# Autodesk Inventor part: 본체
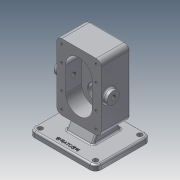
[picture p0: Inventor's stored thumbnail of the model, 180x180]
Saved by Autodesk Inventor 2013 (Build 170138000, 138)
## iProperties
Created: 2020-04
Part Number: 본체
Material: 알루미늄 6061
Document SubType Name: Modeling
Designer: user
Density: 2.71 g/cm^3
Mass: 1478 g
Surface Area: 818.394 cm^2
Volume: 545.387 cm^3
Author: user
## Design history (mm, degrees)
sketch "스케치1"
  geometry: L1 (40, 60)-(-40, 60); L2 (-40, 60)-(-40, -60); L3 (-40, -60)-(40, -60); L4 (40, -60)-(40, 60); L5 (40, 60)-(-40, -60); L6 (-40, 60)-(40, -60); 1 further point
  constraints: 12 end point, 2 midpoint, 2 parallel, 1 horizontal, 1 perpendicular
  dimensions: "d0" = 80 distance of L3.end L2.end; "d1" = 120 distance of L2.end L1.end
extrude "돌출1" new body sketch "스케치1" stored distance "d2" = 53; taper "d3" = 0 deg
fillet "모깎기1" dims "d4" = 9
sketch "스케치2"
  geometry: A1 r 9 centre (-31, -51) between (-40, -51) and (-31, -60) reference; A2 r 9 centre (31, -51) between (31, -60) and (40, -51) reference; A3 r 9 centre (31, 51) between (40, 51) and (31, 60) reference; A4 r 9 centre (-31, 51) between (-31, 60) and (-40, 51) reference; 5 further points
  constraints: 4 coincident
hole "구멍1" sketch "스케치2" at (-31, 51), (31, 51), (31, -51), (-31, -51) diameter "d5" = 4.134; stored, may be unused: countersink angle "d9" = 90 deg, drill point angle "d11" = 118 deg; dims "d6" = 10, "d7" = 4, "d8" = 2, "d10" = 12
sketch "스케치3"
  geometry: L1 (-40, 51)-(-40, -51) reference; L2 (-31, 51)-(-31, 22); L3 (-31, 22)-(-31, -22); A1 r 9 centre (-31, 51) between (-31, 60) and (-40, 51) reference; 3 further points
  constraints: 4 end point, 2 coincident, 1 collinear, 1 parallel
  dimensions: "d12" = 29 distance of L2.start L2.end; "d13" = 44 distance of L2.end L3.end
hole "구멍2" sketch "스케치3" at (-31, 22), (-31, -22) diameter "d14" = 4.134; stored, may be unused: countersink angle "d18" = 90 deg, drill point angle "d20" = 118 deg; dims "d15" = 10, "d16" = 4, "d17" = 2, "d19" = 12
sketch "스케치4"
  geometry: L1 (-24, 22)-(24, 22); L2 (24, 22)-(24, -22); L3 (24, -22)-(-24, -22); L4 (-24, -22)-(-24, 22); L5 (-24, 22)-(24, -22); L6 (24, 22)-(-24, -22); C1 r 24 at (0, 22); C2 r 24 at (0, -22); 1 further point
  constraints: 12 end point, 4 midpoint, 2 centre point, 2 parallel, 1 horizontal, 1 perpendicular
  dimensions: "d21" = 48 distance of L2.end L3.end; "d22" = 44 distance of L1.end L2.end; "d23" = 48 diameter of C1; "d24" = 48 diameter of C2
extrude "돌출2" cut sketch "스케치4" distance "d25" = 29; taper "d26" = 0 deg
sketch "스케치5"
  geometry: L1 (-31, -60)-(31, -60) reference; L2 (0, 0)-(0, 22); C1 r 19 at (0, 22)
  constraints: 2 end point, 1 centre point, 1 coincident, 1 perpendicular
  dimensions: "d27" = 22 distance of L2.start L2.end; "d28" = 38 diameter of C1
extrude "돌출3" join sketch "스케치5" distance "d29" = 17; taper "d30" = 0 deg
sketch "스케치6"
  geometry: A1 r 24 centre (0, 22) between (24, 22) and (-24, 22) reference; 2 further points
  constraints: 1 coincident
hole "구멍3" sketch "스케치6" at (0, 22) diameter "d31" = 17; stored, may be unused: countersink angle "d35" = 90 deg, drill point angle "d37" = 118 deg; dims "d32" = 10, "d33" = 25, "d34" = 15, "d36" = 12
sketch "스케치7"
  geometry: C1 r 12.5 at (0, -22); A1 r 24 centre (0, -22) between (-24, -22) and (24, -22) reference; 1 further point
  constraints: 1 centre point, 1 coincident
  dimensions: "d38" = 25 diameter of C1
extrude "돌출4" cut sketch "스케치7" distance "d39" = 15; taper "d40" = 0 deg
sketch "스케치8"
  geometry: C1 r 8.5 at (0, 0) reference; C2 r 19 at (0, 0) reference; C3 r 14 at (0, 0); 1 further point
  constraints: 1 centre point, 1 coincident
  dimensions: "d41" = 28 diameter of C3
extrude "돌출5" cut sketch "스케치8" distance "d42" = 7.3; taper "d43" = 0 deg
sketch "스케치9"
  geometry: L1 (-53, 0)-(-53, 102) reference; L2 (-53, 51)-(-39, 51); C1 r 11 at (-39, 51); 1 further point
  constraints: 2 end point, 1 centre point, 1 coincident, 1 midpoint, 1 perpendicular
  dimensions: "d44" = 14 distance of L2.start L2.end; "d45" = 22 diameter of C1
extrude "돌출6" join sketch "스케치9" distance "d46" = 8; taper "d47" = 0 deg
sketch "스케치10"
  geometry: C1 r 11 at (0, 0) reference; 2 further points
  constraints: 1 coincident
hole "구멍4" sketch "스케치10" at (0, 0) diameter "d48" = 8.376; stored, may be unused: countersink angle "d52" = 90 deg, drill point angle "d54" = 118 deg; dims "d49" = 10, "d50" = 25, "d51" = 15, "d53" = 12
chamfer "모따기1" distance "d55" = 1; stored, may be unused: second distance "d56" = 2, angle "d57" = 45 deg
chamfer "모따기2" distance "d58" = 0.7; stored, may be unused: second distance "d59" = 2, angle "d60" = 30 deg
fillet "모깎기2" dims "d61" = 0.5
fillet "모깎기3" dims "d62" = 3
fillet "모깎기4" dims "d63" = 3
fillet "모깎기5" dims "d64" = 3
node "작업 평면1"
sketch "스케치11"
  geometry: L1 (-31, -26.5)-(31, -26.5) reference; L2 (60, 56.5)-(-60, 56.5); L3 (-60, 56.5)-(-60, -43.5); L4 (-60, -43.5)-(60, -43.5); L5 (60, -43.5)-(60, 56.5); 2 further points
  constraints: 8 end point, 2 parallel, 1 horizontal, 1 midpoint, 1 perpendicular, 1 vertical alignment
  dimensions: "d66" = 120 distance of L4.end L3.end; "d67" = 100 distance of L3.end L2.end; "d68" = 83 distance between parallel lines of L2 L1
extrude "돌출7" join sketch "스케치11" distance "d69" = 10; taper "d70" = 0 deg
fillet "모깎기6" dims "d71" = 10
fillet "모깎기7" dims "d72" = 10
sketch "스케치12"
  geometry: C1 r 4.5 at (-50, 33.5); C2 r 4.5 at (50, 33.5); C3 r 4.5 at (-50, -46.5); C4 r 4.5 at (50, -46.5); A1 r 10 centre (-50, 33.5) between (-50, 43.5) and (-60, 33.5) reference; A2 r 10 centre (-50, -46.5) between (-60, -46.5) and (-50, -56.5) reference; A3 r 10 centre (50, -46.5) between (50, -56.5) and (60, -46.5) reference; A4 r 10 centre (50, 33.5) between (60, 33.5) and (50, 43.5) reference; 1 further point
  constraints: 4 centre point, 4 coincident
  dimensions: "d73" = 9 diameter of C1; "d74" = 9 diameter of C2; "d75" = 9 diameter of C3; "d76" = 9 diameter of C4
extrude "돌출8" cut sketch "스케치12" stored distance "d77" = 10; taper "d78" = 0 deg
sketch "스케치13"
  geometry: L1 (-60, -23.5)-(-60, 26.5) reference; L2 (51, -26.5)-(-51, -26.5) reference; L3 (-51, -26.5)-(-57, -26.5) reference; L4 (-80, -33.5)-(-80, 46.5) reference; L5 (-80, 51)-(-80, 42) reference; L6 (-80, -29)-(-80, -38) reference; L7 (-80, -33.5)-(-80, -43.5) reference; L8 (-80, 56.5)-(-80, 46.5) reference; L9 (-80, -43.5)-(-90, -43.5) reference; L10 (-80, -43.5)-(-80, -26.5); L11 (-80, -26.5)-(-60, -14.953); L12 (-60, 14.953)-(-80, 26.5); A1 r 3 centre (-57, -23.5) between (-60, -23.5) and (-57, -26.5) reference; 1 further point
  constraints: 6 end point, 4 point on line
  dimensions: "d79" = 17 distance of L7.end L10.end; "d80" = 60 deg angle of L4 L11; "d81" = 53 distance of L10.end L12.end; "d82" = 60 deg angle of L4 L12
extrude "돌출9" join sketch "스케치13" stored distance "d83" = 48; taper "d84" = 0 deg
fillet "모깎기8" dims "d85" = 3
fillet "모깎기9" dims "d86" = 3
fillet "모깎기10" dims "d87" = 3
sketch "스케치14"
  geometry: L1 (-60, 33.5)-(-60, -46.5) reference; L2 (-50, -56.5)-(50, -56.5) reference; 2 further points
  constraints: 1 other
  dimensions: "d88" = 60 distance from line of L1 point (0, -46.5); "d89" = 10 distance from line of L2 point (0, -46.5)
feature "엠보싱1" sketch "스케치14" dims "d0" = 80, "d1" = 120, "d90" = 0.5, "d91" = 0
node "솔리드1"
mirror "대칭1"
mirror "대칭2"
